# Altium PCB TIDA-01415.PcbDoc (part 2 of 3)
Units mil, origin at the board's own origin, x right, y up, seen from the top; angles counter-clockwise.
Board outline 3820.95 x 4648 mil, 4 copper layers (Top Layer, GND, PWR, Bottom Layer), stack 5.6 mil thick; 255 components, 113 nets, 599 pads, 415 vias.
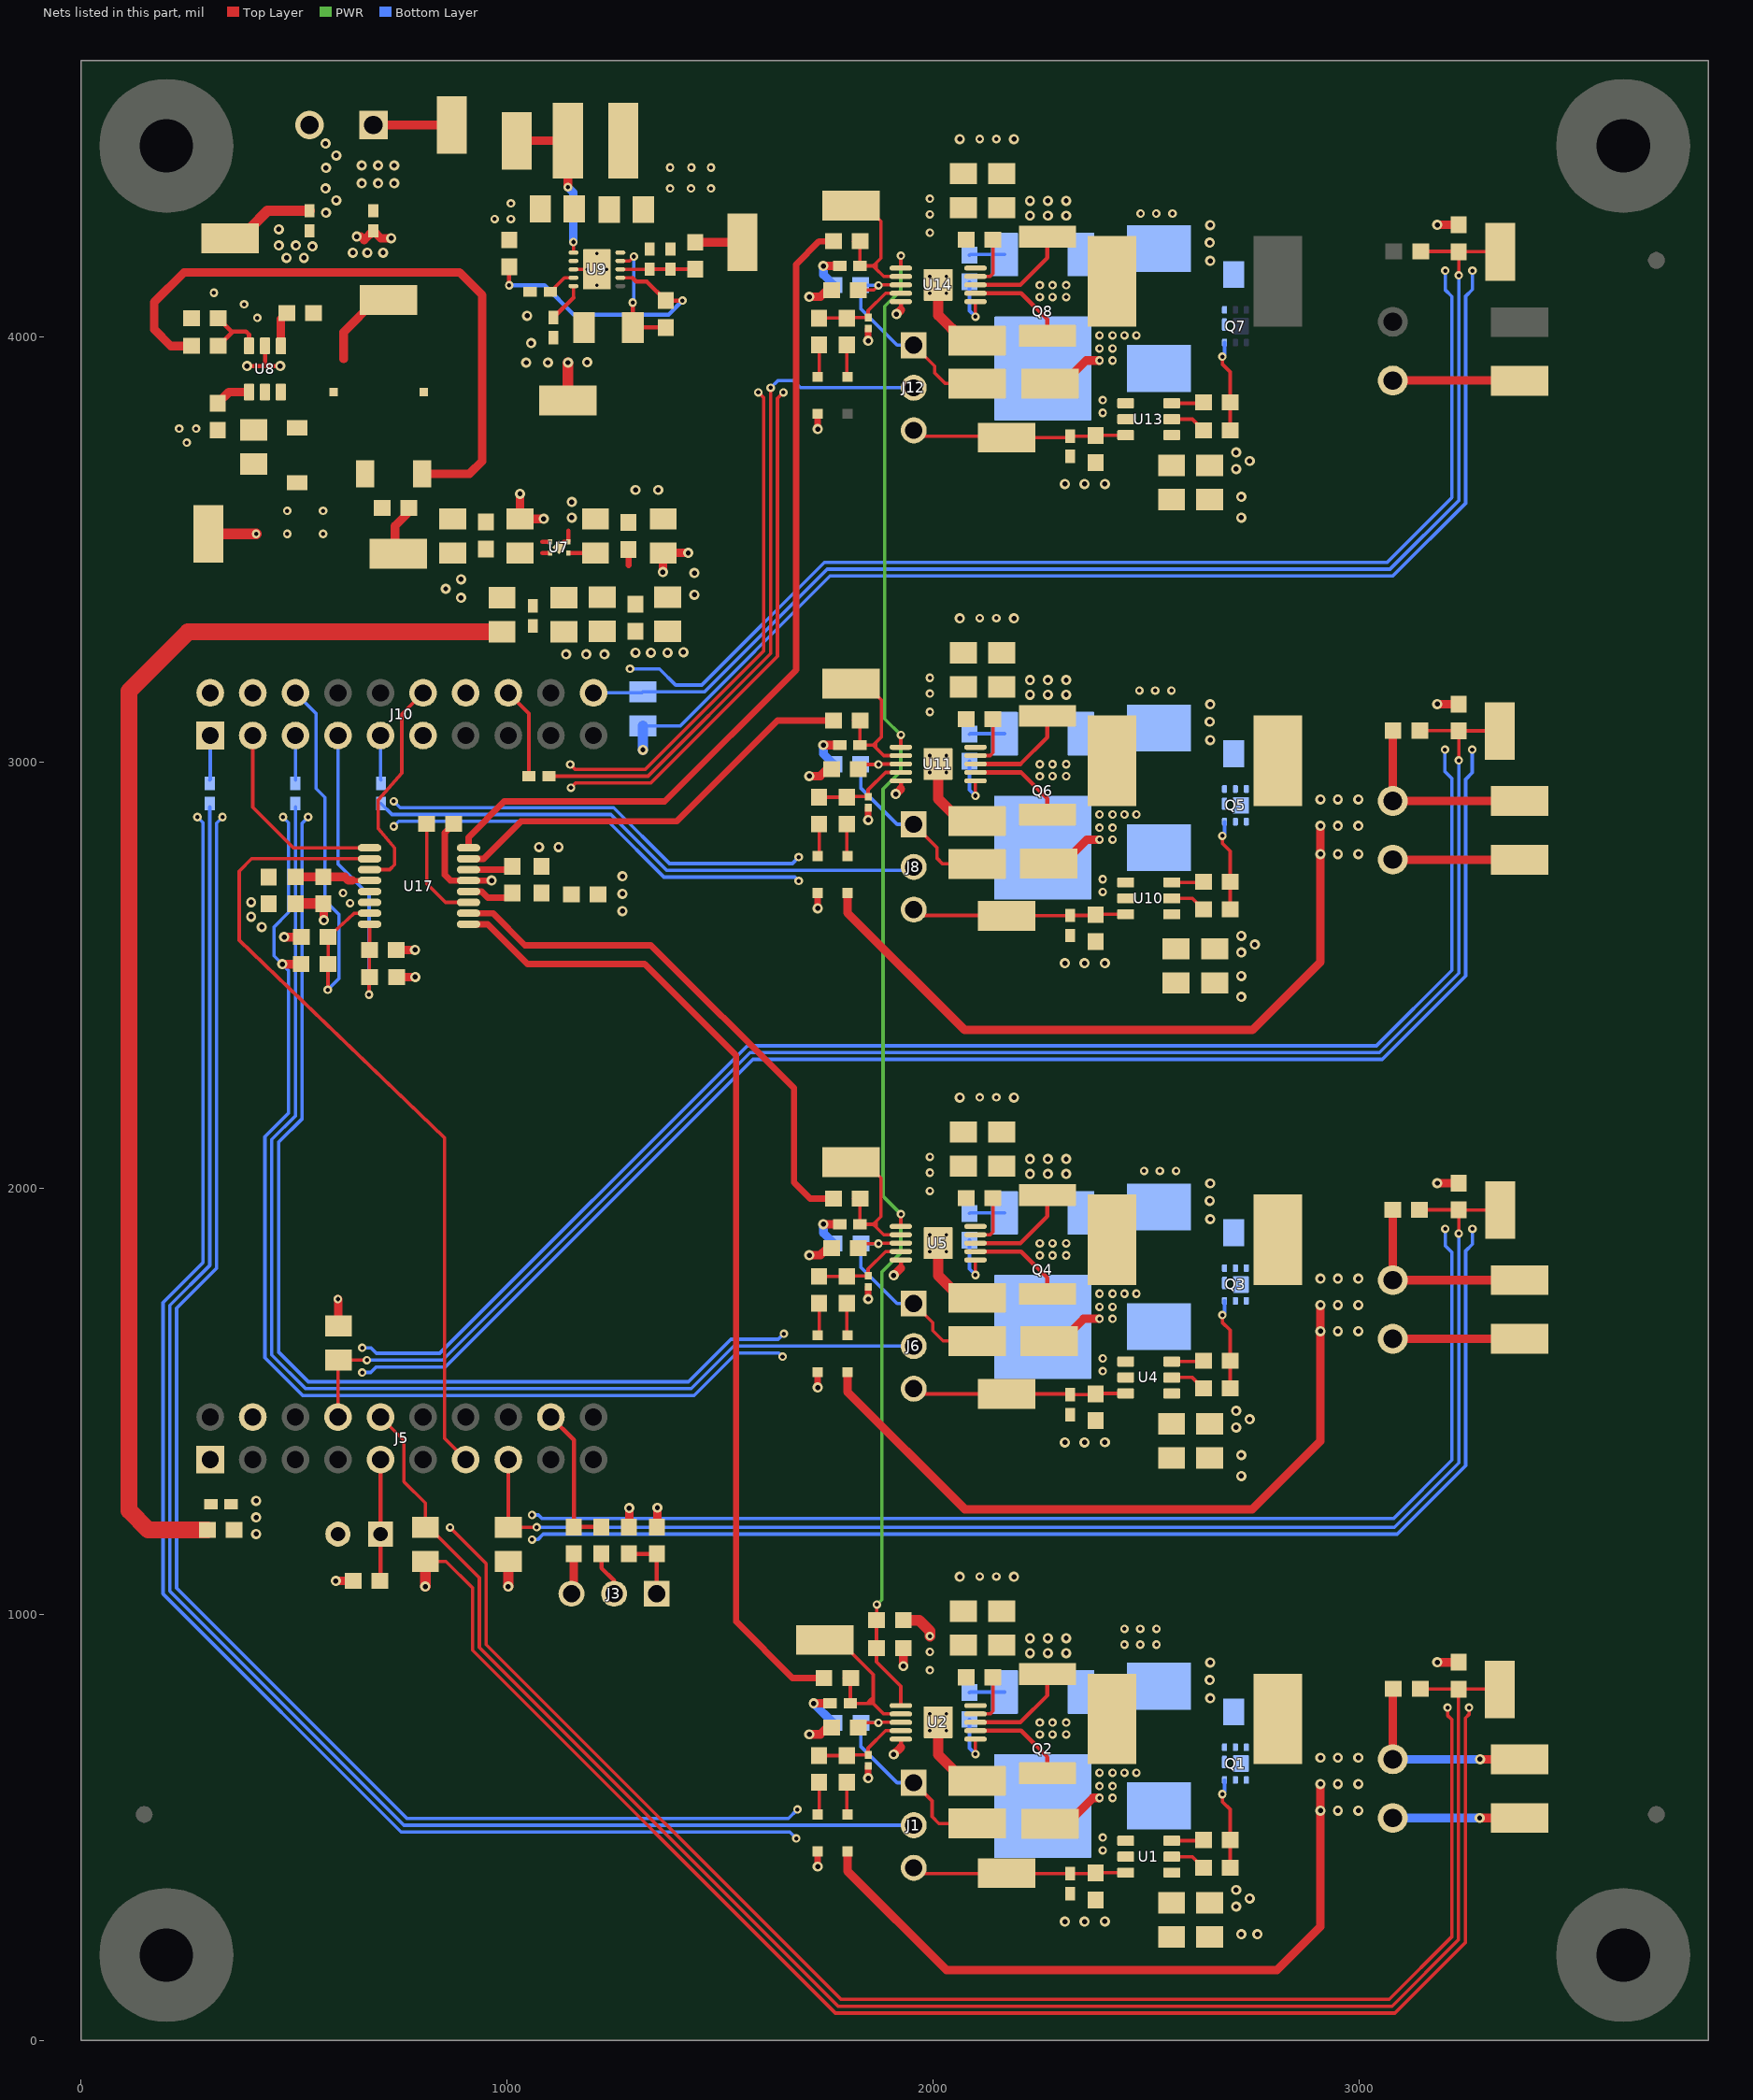
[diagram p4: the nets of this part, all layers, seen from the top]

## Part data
BLED+ BLED- GLED+ GLED- GND GND GND1 GND1 GND1 GND1 IADJ1 IADJ2 IADJ3 IADJ4 PWM1 PWM2 PWM3 PWM4 RLED+ RLED- SH1 SH2 SH3 SH4 SW1 SW2 SW3 SW4 SW5 SW6 TP1 TP3 VFB1 VFB2 VFB3 VFB4 VIN+ VIN- WLED+ WLED-: "Test Point, Miniature, SMT"
C1 C15 C46 C59 C85 C86 C87 C88: "CAP, CERM, 0.1 µF, 50 V, +/- 10%, X7R, 0805"
C2 C16 C47 C60: "CAP, CERM, 1 µF, 50 V, +/- 10%, X7R, 0805"
C3 C14 C45 C58 C74: "CAP, CERM, 1 µF, 16 V, +/- 10%, X7R, 0603"
C4 C5 C17 C18 C34 C41 C48 C49 C61 C62: "CAP, CERM, 2.2 µF, 50 V, +/- 10%, X7R, 0805"
C6 C19 C50 C63: "CAP, CERM, 0.01 µF, 50 V, +/- 10%, X7R, 0805"
C7 C20 C51 C64: "CAP, CERM, 470 pF, 50 V, +/- 10%, X7R, AEC-Q200 Grade 1, 0201"
C27: "CAP, CERM, 0.33 µF, 16 V, +/- 10%, X7R, 0603"
C28 C29 C30 C31 C35 C36 C101 C102: "CAP, CERM, 2.2 µF, 16 V, +/- 10%, X7R, 0805"
C32: "CAP, CERM, 22 µF, 16 V, +/- 10%, X5R, 1206"
C33 C38 C43 C78: "CAP, CERM, 10 µF, 10 V, +/- 20%, X6S, AEC-Q200 Grade 2, 0603"
C37: "CAP, CERM, 0.047 µF, 25 V, +/- 10%, X7R, AEC-Q200 Grade 1, 0603"
C39: "CAP, CERM, 0.1 µF, 25 V, +/- 10%, X7R, 0603"
C40: "CAP, CERM, 10 µF, 16 V, +/- 10%, X7S, AEC-Q200 Grade 1, 0805"
C42: "CAP, CERM, 0.056 µF, 16 V, +/- 10%, X7R, 0402"
C44: "CAP, CERM, 0.1 µF, 10 V, +/- 10%, X5R, 0402"
C77 C79: "CAP, CERM, 0.1 µF, 50 V, +/- 10%, X7R, 0603"
C80: "CAP, CERM, 0.15 µF, 25 V, +/- 10%, X7R, 0603"
C89 C90 C91 C92: "CAP, CERM, 0.1 µF, 25 V, +/- 20%, X7R, 0402"
C97 C98 C99 C100: "CAP, CERM, 15 pF, 50 V, +/- 5%, C0G/NP0, 0402"
D1 D3 D4 D6 D8 D10 D11 D13: "Diode, Schottky, 10 V, 0.75 A, SOD-323"
D2 D5 D9 D12: "Diode, Schottky, 60 V, 5 A, SMC"
D7: "Diode, Schottky, 100 V, 1 A, SOD-123FL"
FID1 FID2 FID3 FID4 FID5 FID6: "Fiducial mark.  There is nothing to buy or mount."
H1 H2 H3 H4: "Machine Screw, Round, #4-40 x 1/4, Nylon, Philips panhead"
H5 H6 H7 H8: "Standoff, Hex, 0.5\"L #4-40 Nylon"
J1 J3 J6 J8 J12: "Header, 2.54mm, 3x1, Tin, TH"
J2 J7 J9 J13: "Conn Term Block, 2POS, 3.5mm, TH"
J4: "Header, 100mil, 2x1, TH"
J5 J10: "Header, 100mil, 10x2, TH"
J14: "Conn Term Block, 2POS, 3.81mm, TH"
L1 L2 L8 L9: "Inductor, Shielded Drum Core, Ferrite, 47 µH, 2.7 A, 0.076 ohm, SMD"
L3: "Inductor, Shielded Drum Core, Ferrite, 15 µH, 1.15 A, 0.07 ohm, SMD"
L4 L5 L10: "Ferrite Bead, 1000 ohm @ 100 MHz, 0.6 A, 0603"
L6: "Ferrite Bead, 220 ohm @ 100 MHz, 0.45 A, 0402"
L7: "Inductor, Drum Core, Ferrite, 330 µH, 0.17 A, 6 ohm, SMD"
LBL1: library part THT-14-423-10, "Thermal Transfer Printable Labels, 0.650\" W x 0.200\" H - 10,000 per roll"
Logo2: library part Pb-Free
Q1 Q3 Q5 Q7: "MOSFET, N-CH, 100 V, 4.5 A, DQK0006C (WSON-6)"
Q2 Q4 Q6 Q8: "MOSFET, P-CH, -100 V, -4.6 A, DPAK"
R1: "RES, 5.62 k, 1%, 0.1 W, 0603"
R2: "RES, 49.9 k, 1%, 0.1 W, 0603"
R3 R4 R17 R18 R41 R42 R53 R54: "RES, 1.0, 5%, 0.1 W, 0603"
R5 R19 R43 R55: "RES, 0.3, 1%, 2 W, 2512"
R6 R7 R20 R21 R44 R45 R56 R57: "RES, 10.0 k, 1%, 0.1 W, 0603"
R8 R22 R46 R58: "RES, 470, 5%, 0.063 W, 0402"
R9 R23 R47 R59: "RES, 3.16 M, 1%, 0.1 W, 0603"
R10 R24 R48 R60: "RES, 4.53 k, 1%, 0.1 W, 0603"
R12 R25 R30 R33 R49 R61: "RES, 110 k, 1%, 0.1 W, 0603"
R14 R28 R52 R64: "RES, 14.0 k, 1%, 0.1 W, 0603"
R15 R16: "RES, 0, 5%, 0.063 W, 0402"
R29 R39 R65 R71 R86 R87 R88 R89: "RES, 100 k, 1%, 0.1 W, 0603"
R31: "RES, 30.0 k, 1%, 0.1 W, 0603"
R32 R94 R95 R96 R97: "RES, 100, 1%, 0.1 W, 0603"
R34: "RES, 887 k, 1%, 0.063 W, 0402"
R35: "RES, 1.50 k, 1%, 0.1 W, 0603"
R36: "RES, 12.4 k, 1%, 0.1 W, 0603"
R37: "RES, 124 k, 1%, 0.063 W, 0402"
R38: "RES, 182 k, 1%, 0.063 W, 0402"
R75 R76 R77 R78 R79 R80: "RES, 0, 5%, 0.1 W, 0603"
R81: "RES, 412, 1%, 0.25 W, 1206"
R99 R100: "RES, 10.0, 1%, 0.1 W, 0603"
U1 U4 U10 U13: "Single-Channel High-Speed Low-Side Gate Driver (with 4-A Peak Source and 8-A Peak Sink), DBV0006A (SOT-6)"
U2 U5 U11 U14: "PFET Buck Controller for High Power LED Drives, 10-pin eMSOP, Pb-Free"
U7: "250-mA Ultra-Low-Noise, Low-IQ LDO, DQN0004A (X2SON-4)"
U8: "Wide Input Voltage Range Buck Regulator with High Efficiency Sleep Mode, DDC0006A (SOT-6)"
U9: "3V-65V, 150mA Synchronous Buck Converter With Ultra-Low IQ, DRC0010J (VSON-10)"
U17: "12-Bit, Quad Channel, Ultra-Low Glitch, Voltage Output DAC with 2.5V, 2ppm/degC Internal Reference, PW0016A (TSSOP-16)"
ZZ1: library part AssemblyNoteLabel
ZZ2 ZZ3 ZZ4: library part AssemblyNote

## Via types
v1: diameter 24, hole 12, Top Layer to Bottom Layer, tented both sides, 213 vias
v2: diameter 20, hole 10, Top Layer to Bottom Layer, tented both sides, 182 vias
v3: diameter 19.68, hole 7.87, Top Layer to Bottom Layer, 20 vias

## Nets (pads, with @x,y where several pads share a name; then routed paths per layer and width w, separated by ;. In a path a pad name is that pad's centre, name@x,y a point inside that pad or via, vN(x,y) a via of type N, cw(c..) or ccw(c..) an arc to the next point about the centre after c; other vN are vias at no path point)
+3.3V_A: C31.1 L5.2 R32.2 R39.2 R65.2 R71.2 R99.1 | length 170.6
  Top Layer w20: v1(476.65,2590.15) R65.2@516.82,2590.15 R65.2@520.82,2590.15 ; v1(598,1078.5) R39.2@638.5,1078.5 ; R71.2@739.81,2560.15 v1(783.98,2560.15) ; R32.2@1286.46,1207.93 1287,1208.47 v1(1287,1249.5)
  other v1: 1271,2651 1271,2692 1271,2733 1301.61,3640 1355,3640
+3.3V_D: C102.1 L10.2 R100.1
  other v1: 424,2614 399,2638 399,2672 1301.77,3258 1338,3258 1377,3258 1414,3259
+3.3V_LP: C36.1 C43.1 C44.2 J5.1 L6.2 | length 3061.1
  Top Layer w40: C43.1@296.5,1198.49 157.51,1198.49 112,1244 112,3168 251,3307 C36.1@988.13,3307
+3.6V: C28.1 C32.1 C33.1 L3.2 L4.1 R30.2 TP1.1 | length 1657
  Top Layer w20: R30.2@259.11,3978.02 210.48,3978.02 171.5,4017 171.5,4080.77 241.73,4151 888,4151 941.78,4097.22 941.78,3707.78 912,3678 C32.1@800.43,3678 ; TP1.1@745,3490.07 737,3498.07 737,3555.55 769.49,3588.04 C33.1@769.49,3598
+10V: C1.1 C2.1 C15.1 C16.1 C37.1 C40.1 C46.1 C47.1 C59.1 C60.1 L7.2 R34.2 TP3.1 U1.1 U4.1 U10.1 U13.1 | length 111.2
  Top Layer w20: C37.1@1442,4221.5 TP3.1@1552.5,4221.5
  Top Layer w40: TP3.1@1552.5,4221.5 TP3.1@1553,4221
  other v1: 2712,314 2743.77,333 2712,353 2712,1439 2743.77,1458 2712,1478 2724.25,2553.98 2756.01,2572.98 2724.25,2592.98 2712,3689 2743.77,3708 2712,3728
  other v2: 1383,4348 1432,4348 1479,4348 1383,4397 1433,4397 1479,4397
BLED+: BLED+.1 C50.1 D10.2 J9.1 L8.2 Q5.1 Q5.2 Q5.5 Q5.6 Q5.8 R49.2 | length 2119.3
  Top Layer w20: D10.2@1799.43,2693.69 1799.43,2647.47 2075,2371.9 2750,2371.9 2910,2531.9 v1(2910,2785) v1(2910,2851.53) ; R49.2@3080,3074.5 J9.1@3080,2909.79 BLED+.1@3377.79,2909.79
  other v1: 2951,2785 2999,2785 2951,2851.53 2999,2851.53 2910,2913.53 2951,2913.53 2999,2913.53
CS_ADC: J10.4
CS_DAC: J10.6 R65.1 R79.2 U17.15 | length 993
  Top Layer w8: v2(579,2466.5) 579.5,2466.99 R79.2@579.5,2526.5 579.81,2526.81 R65.1@579.81,2590.15 641,2646 U17.15@677.17,2646.18
  Bottom Layer w8: J10.6@502.99,3163.49 551.57,3114.92 551.57,2939 572.3,2918.27 572.3,2676.72 605,2644.02 605,2492.5 v2(579,2466.5)
DIN: J10.12 U17.11 | length 522.9
  Top Layer w8: U17.11@677.17,2748.54 724.5,2748.54 736,2760.04 736,2799.91 697.71,2844.75 697.71,2913 753,2975.25 753,3113.5 J10.12@802.99,3163.49
DOUT_ADC: J10.14
DRDY: J10.11
GLED+: C19.1 D6.2 GLED+.1 J7.1 L2.2 Q3.1 Q3.2 Q3.5 Q3.6 Q3.8 R25.2 | length 2105.6
  Top Layer w20: D6.2@1799.43,1568.69 1799.43,1522.47 2075,1246.9 2750,1246.9 2910,1406.9 v1(2910,1665) v1(2910,1726.53) ; R25.2@3080,1949.5 J7.1@3080,1784.79 GLED+.1@3364,1784.79
  other v1: 2951,1665 2999,1665 2951,1726.53 2999,1726.53 2910,1788.53 2951,1788.53 2999,1788.53
GND: C28.2 C29.2 C30.2 C31.2 C32.2 C33.2 C34.2 C35.2 C36.2 C38.2 C39.2 C40.2 C41.2 C42.2 C43.2 C44.1 C74.2 C77.1 C78.2 C79.1 C80.1 C85.1 C86.1 C87.1 C88.1 C101.2 C102.2 D7.2 GND.1 J3.3 J4.2 J5.4 J10.2 R14.1 R16.2 R28.1 R31.1 R37.1 R38.1 R52.1 R64.1 R79.1 R80.1 R81.1 U7.2 U7.5 U8.2 U9.3 U9.10 U9.11 U17.5 U17.6 U17.13 U17.14 | length 43613.1
  Top Layer w8: C85.1@808,1124.5 856.76,1124.5 919,1062.26 919,916 1771,64 3085,64 3250.36,229.36 3250.36,756.47 3259,765.11 v2(3259,781) ; v2(866.15,1204) 951,1119.15 951,929.25 1784.25,96 3071.75,96 3218.36,242.61 3218.36,753.18 3208.54,763 v2(3208.54,781) ; v2(1148.48,2995.45) 1159.93,2984 1324.37,2984 1603,3262.63 1603,3856 v2(1590,3869) ; v2(1150.02,2941) 1161,2952 1337.63,2952 1635,3249.37 1635,3855 v2(1649,3869) v2@1650,3868 ; U9.3@1155.88,4158 v3(1188.36,4158) U9.11@1211,4158
  Top Layer w10: v1(389.5,3931) 433.5,3931 ; U8.2@431.5,3978.13 431.5,3933 433.5,3931 ; v1(467.5,3931) 433.5,3931 ; U7.5@1122.5,3505 1126.92,3505 1126.92,3511.31 1133.41,3517.8 U7.2@1143.56,3517.8 1143.56,3544.99
  Top Layer w15: C80.1@874.5,2856 854,2835.5 854,2736 867.05,2722.95 U17.5@909.46,2722.95 v1(963.95,2722.95) ; U17.6@909.46,2748.54 1004.2,2748.54 C77.1@1012.31,2756.65
  Top Layer w20: v1(472.34,2526.5) R79.1@516.5,2526.5 ; C79.1@569.97,2668 v1(570,2630) ; C79.1@570.47,2666.5 C79.1@570.97,2667 ; v2(602.99,1740.31) 604,1739.3 C87.1@604,1677 ; R80.1@740.5,2496.5 v1(784.66,2496.5) ; v1(1030.48,3631) C29.2@1030.48,3572.09 v1(1086.27,3572.09) ; J3.3@1151.46,1048.5 1156.46,1053.5 C39.2@1156.46,1142 ; C38.2@1351.46,1204.99 1353,1206.54 v1(1353,1250.5) ; v1(1366,3447) 1366,3491.59 C31.2@1366.5,3492.09 v1(1425.41,3492.09) ; v1(3184.5,887.39) R14.1@3235,887.39 ; v1(3184.5,2012.39) R28.1@3235,2012.39 ; v1(3184.5,3137.39) R52.1@3235,3137.39 ; v1(3184.5,4262.39) R64.1@3235,4262.39
  Top Layer w25: GND.1@299,3536.71 410.71,3536.71 v2(411,3537) ; C78.2@497.31,2668.66 C79.1@568.31,2668.66 ; v1(808,1065.5) C85.1@808,1124.5 ; v1(1003,1065.5) C86.1@1003,1124.5 ; GND.1@1142.53,3850 1143,3850.47 v1(1143,3939)
  Bottom Layer w8: v2(273,2872) 286,2859 286,1826.13 192.16,1732.29 192.16,1048.21 751.48,488.9 1664.1,488.9 v2(1679,474) ; v2(332,2872) 318,2858 318,1812.87 224.16,1719.03 224.16,1061.47 764.73,520.9 1660.9,520.9 v2(1682,542) ; v2(474,2872) 487,2859 487,2648 452.65,2613.65 452.65,2546.18 v1(472.34,2526.5) 487,2511.84 487,2177.13 431.47,2121.6 431.47,1602.85 520.32,1514 1439.25,1514 1539.15,1613.9 1638.1,1613.9 v2(1647,1605) ; v2(533,2872) 519,2858 519,2163.87 463.47,2108.35 463.47,1616.1 533.58,1546 1426,1546 1525.9,1645.9 1636.9,1645.9 v2(1650,1659) ; v2(659.88,1567.99) 680,1567.99 693,1580.99 855.25,1580.99 1577.25,2303 3055,2303 3251,2499 3251,2960.5 3266.5,2976 v2(3266.5,3030.5) ; v2(659.88,1625.99) 680,1625.99 693,1612.99 841.99,1612.99 1564,2335 3041.75,2335 3219,2512.25 3219,2962.5 3202.5,2979 v2(3202.5,3030.5) ; v2(734,2850) 746,2862 1237.37,2862 1368.37,2731 1676,2731 v2(1685,2722) ; v2(734,2909) 749,2894 1250.63,2894 1381.63,2763 1670,2763 v2(1685,2778) ; v2(1058.88,1175.5) 1071.99,1175.5 1084.99,1188.5 3090.5,1188.5 3251,1349 3251,1853.45 3267,1869.45 v2(3267,1905) ; v2(1058.88,1233.5) 1074,1233.5 1082,1225.5 3082.24,1225.5 3219,1362.25 3219,1850 3203,1866 v2(3203,1905) ; v2(1288.92,3220) 1358,3220 1396,3182 1457.37,3182 1745.37,3470 3066.91,3470 3219,3622.09 3219,4094 3203,4110 v2(3203,4155) ; C88.1@1319,3086 1406.63,3086 1758.63,3438 3080.16,3438 3251,3608.84 3251,4095 3267,4111 v2(3267,4155)
  Bottom Layer w25: v1(1319,3029.88) C88.1@1319,3086
  other v1: 411,1188.5 411,1227.5 411,1266.5 1075,2801.5 1121,2801.5 1139,3254 1186,3254 1229,3254 892,3387 1440,3394 856,3408 892,3430 1440,3445 1152,3575 1152,3612 1045,3939 1096,3939 1188.36,3940 1056.74,3985 1047,4049 482,4185 523,4185 543,4212 464,4214 504,4214 464,4252
  other v2: 631.31,2670 615,2693.69 484,3537 568,3537 484,3591 568,3591 413.5,4044 382.5,4076 311.5,4103
  other v3: 1211,4120.6 1233.64,4158 1211,4195.4
GND1: BLED-.1 C1.2 C2.2 C4.2 C5.2 C6.2 C7.2 C15.2 C16.2 C17.2 C18.2 C19.2 C20.2 C46.2 C47.2 C48.2 C49.2 C50.2 C51.2 C59.2 C60.2 C61.2 C62.2 C63.2 C64.2 C89.1 C90.1 C91.1 C92.1 C97.2 C98.2 C99.2 C100.2 D2.2 D5.2 D9.2 D12.2 GLED-.1 GND1.1 J2.2 J7.2 J9.2 J13.2 J14.2 Q1.4 Q1.7 Q3.4 Q3.7 Q5.4 Q5.7 Q7.4 Q7.7 R1.1 R6.1 R7.1 R16.1 R20.1 R21.1 R44.1 R45.1 R56.1 R57.1 RLED-.1 U1.4 U1.5 U2.5 U2.11 U4.4 U4.5 U5.5 U5.11 U10.4 U10.5 U11.5 U11.11 U13.4 U13.5 U14.5 U14.11 VIN-.1 WLED-.1 | length 2835.1
  Top Layer w10: 1924.75,687.89 U2.5@1924.75,707.17 ; 1924.75,1812.89 U5.5@1924.75,1832.17 ; 1924.75,2937.89 U11.5@1924.75,2957.17 ; 1924.75,4062.9 U14.5@1924.75,4082.17
  Top Layer w15: v1(1847.95,615.31) C7.2@1847.95,644.01 ; v1(1847.95,1740.31) C20.2@1847.95,1769.01 ; v1(1847.95,2865.31) C51.2@1847.95,2894.01 ; v1(1847.95,3990.31) C64.2@1847.95,4019.01
  Top Layer w20: v1(1719.98,791) C89.1@1758.76,791 ; v1(1742.98,1916) C90.1@1781.76,1916 ; v1(1742.98,3041) C91.1@1781.76,3041 ; v1(1742.98,4166) C92.1@1781.76,4166 ; v1(1908,671.14) 1924.75,687.89 ; v1(1908,1796.14) 1924.75,1812.89 ; v1(1913,2926.14) 1924.75,2937.89 ; v1(1914.62,4052.76) 1924.75,4062.9 ; J7.2@3080,1647 GLED-.1@3360,1647 ; J9.2@3080,2772 BLED-.1@3378,2772 ; J13.2@3080,3897 WLED-.1@3377,3897 ; v1(3284,522) RLED-.1@3378,522
  Top Layer w25: VIN-.1@396,4254 437.62,4295.62 R16.1@536,4295.62 ; R1.1@1930.65,986.12 1967.88,986.12 1993,961 v2(1993,949) ; U2.11@2012.35,746.54 2012.35,670.65 2074,609 GND1.1@2104,609 ; U5.11@2012.35,1871.54 2012.35,1795.65 2065,1743 GND1.1@2104,1743 ; U11.11@2012.35,2996.54 2012.35,2914.65 2064,2863 GND1.1@2101,2863 ; U14.11@2012.35,4121.54 2012.35,4050.65 2072,3991 GND1.1@2104,3991
  Bottom Layer w20: v1(1719.98,791) 1765.53,745.45 R7.1@1768.06,745.45 ; v1(1742.98,1916) 1742.98,1895.52 R20.1@1768.06,1870.45 ; v1(1742.98,3041) 1742.98,3020.52 R44.1@1767.5,2996 ; v1(1742.98,4166) 1742.98,4145.52 R56.1@1767.5,4121 ; J2.2@3080,522 v1(3284,522)
  other v1: 2724,248.9 2762,249 2310,278.82 2356,278.82 2404,279 2651,802.9 2650,845.9 2651,886.9 2063,1088.53 2190.55,1088.53 2724,1324.9 2724,1373.9 2310,1403.82 2356,1403.82 2404,1404 2651,1927.9 2650,1970.9 2651,2011.9 2063,2213.53 2190.55,2213.53 2724,2449.9 2724,2498.9 2310,2528.82 2356,2528.82 2404,2529 2651,3052.9 2650,3095.9 2651,3136.9 2063,3338.53 2190.55,3338.53 2724,3574.9 2724,3623.9 2310,3653.82 2356,3653.82 2404,3654 2651,4177.9 2650,4220.9 2651,4261.9 575,4291 599,4320 574,4348 575,4396.42 599,4425.42 574,4453.42 2063,4463.53 2190.55,4463.53
  other v2: 2399,446 2399,476 1993,869 1993,912 2450,929 2487,929 2525,929 2450,966 2487,966 2525,966 2110,1089 2149,1089 2399,1571 2399,1601 1993,1994 1993,2037 2496,2041 2533,2041 2571,2041 1993,2074 2110,2214 2149,2214 2399,2696 2399,2726 1993,3119 1993,3162 2485,3169 2522,3169 2560,3169 1993,3199 2110,3339 2149,3339 2399,3821 2399,3851 1993,4244 1993,4287 2487.65,4289 2524.65,4289 2562.65,4289 1993,4324 2110,4464 2149,4464
  other v3: 1992.67,726.85 2032.04,726.85 1992.67,766.22 2032.04,766.22 1992.67,1851.85 2032.04,1851.85 1992.67,1891.22 2032.04,1891.22 1992.67,2976.85 2032.04,2976.85 1992.67,3016.22 2032.04,3016.22 1992.67,4101.85 2032.04,4101.85 1992.67,4141.22 2032.04,4141.22
IADJ1: R94.2 U17.1 | length 2346.3
  Top Layer w15: U17.1@909.46,2620.59 954.41,2620.59 1048,2527 1323,2527 1538,2312 1538,983 1670.17,850.83 R94.2@1744.18,850.83
IADJ2: R95.2 U17.2 | length 1263.6
  Top Layer w15: U17.2@909.46,2646.18 966.82,2646.18 1042,2571 1338,2571 1674,2235 1674,2014 1711.67,1976.33 R95.2@1766.18,1976.33
IADJ3: R96.2 U17.7 | length 991.2
  Top Layer w15: U17.7@909.46,2774.13 945.13,2774.13 1033,2862 1398,2862 1634.83,3098.83 R96.2@1766.18,3098.83
IADJ4: R97.2 U17.8 | length 2018.9
  Top Layer w15: U17.8@909.46,2799.72 909.46,2824.46 993.5,2908.5 1370.02,2908.5 1679,3217.48 1679,4169.75 1733.09,4223.83 R97.2@1766.18,4223.83
LDAC: J10.7 R71.1 R80.2 U17.16 | length 805.8
  Top Layer w8: v2(676,2455) 676,2494 678,2496 R80.2@677.5,2496.5 676.82,2497.18 R71.1@676.82,2560.15 677.17,2560.51 U17.16@677.17,2620.59
  Bottom Layer w8: J10.7@602.99,3063.49 602.99,2761.57 676,2688.56 v2(676,2455)
NetC3_2: C3.2 U2.9 | length 123
  Top Layer w8: U2.9@2099.95,766.22 2134.08,766.22 2141.25,773.39 C3.2@2141.25,852.17
NetC7_1: C7.1 R9.2 R10.1 U2.4 | length 225.4
  Top Layer w8: R9.2@1732.95,668.5 R10.1@1797.95,668.5 1799.45,669.99 C7.1@1847.95,669.99 1847.95,686.09 1888.71,726.85 U2.4@1924.75,726.85
NetC14_2: C14.2 U5.9 | length 123
  Top Layer w8: U5.9@2099.95,1891.22 2134.08,1891.22 2141.25,1898.39 C14.2@2141.25,1977.17
NetC20_1: C20.1 R23.2 R24.1 U5.4 | length 225.4
  Top Layer w8: R23.2@1732.95,1793.5 R24.1@1797.95,1793.5 1799.45,1794.99 C20.1@1847.95,1794.99 1847.95,1811.09 1888.71,1851.85 U5.4@1924.75,1851.85
NetC27_1: C27.1 D7.1 L3.1 SW5.1 U8.6 | length 198.7
  Top Layer w20: 616.26,3948 616.26,4010.26 692.42,4086.42 SW5.1@721.11,4086.42
NetC27_2: C27.2 U8.1 | length 82.7
  Top Layer w20: U8.1@468.9,3978.13 468.9,4040.9 C27.2@483,4055
NetC29_1: C29.1 L4.2 U7.3 U7.4 | length 37.7
  Top Layer w10: 1082.5,3492.2 U7.4@1101.44,3492.2 ; 1082.64,3517.8 U7.3@1101.44,3517.8
NetC30_1: C30.1 C35.1 C101.1 L5.1 L6.1 L10.1 U7.1 | length 100.5
  Top Layer w10: U7.1@1143.56,3492.2 1143.67,3492.09 C30.1@1207.5,3492.09
  Top Layer w15: 1285.5,3464 L5.1@1285.5,3500.5
NetC37_2: C37.2 R34.1 R37.2 U9.8 | length 176.1
  Top Layer w8: U9.8@1266.12,4158 1334.62,4158 R37.2@1335,4158.38 R34.1@1384,4158.38 1441.87,4158.38 C37.2@1442,4158.5
NetC38_1: C38.1 J3.1 R32.1 | length 158.5
  Top Layer w10: R32.1@1286.46,1142 C38.1@1351.46,1142 J3.1@1351.46,1048.5
NetC42_1: C42.1 U9.4 | length 68.1
  Top Layer w8: C42.1@1101.62,4105 1134.94,4138.32 U9.4@1155.88,4138.32
NetC45_2: C45.2 U11.9 | length 123
  Top Layer w8: U11.9@2099.95,3016.22 2134.08,3016.22 2141.25,3023.39 C45.2@2141.25,3102.17
NetC51_1: C51.1 R47.2 R48.1 U11.4 | length 225.4
  Top Layer w8: R47.2@1732.95,2918.5 R48.1@1797.95,2918.5 1799.45,2919.99 C51.1@1847.95,2919.99 1847.95,2936.09 1888.71,2976.85 U11.4@1924.75,2976.85
NetC58_2: C58.2 U14.9 | length 123
  Top Layer w8: U14.9@2099.95,4141.22 2134.08,4141.22 2141.25,4148.39 C58.2@2141.25,4227.17
NetC64_1: C64.1 R59.2 R60.1 U14.4 | length 225.4
  Top Layer w8: R59.2@1732.95,4043.5 R60.1@1797.95,4043.5 1799.45,4044.99 C64.1@1847.95,4044.99 1847.95,4061.09 1888.71,4101.85 U14.4@1924.75,4101.85
NetC74_1: C74.1 C77.2 R99.2 U17.4 | length 113.2
  Top Layer w15: U17.4@909.46,2697.36 940.17,2697.36 954.53,2683 1001.66,2683 C77.2@1012.31,2693.66
NetC78_1: C78.1 C79.2 R100.2 U17.12 | length 177.5
  Top Layer w12: 636.45,2722.95 U17.12@677.17,2722.95
  Top Layer w20: C78.1@503.31,2731.65 C79.2@568.31,2731.65 618.85,2731.65 627.55,2722.95 636.45,2722.95
NetC80_2: C80.2 U17.3 | length 256.6
  Top Layer w8: C80.2@811.5,2856 811.5,2715.5 855.23,2671.77 U17.3@909.46,2671.77
NetC89_2: C89.2 IADJ1.1 R94.1 U2.2 | length 438.7
  Top Layer w8: IADJ1.1@1746.31,940 1778.64,940 1859.75,858.88 1859.75,805.1 ; R94.1@1791.42,850.83 1806,836.26 C89.2@1806,791 1845.65,791 ; U2.2@1924.75,766.22 1884.53,766.22 1859.75,791 ; 1845.65,791 1859.75,791 ; 1845.65,791 1853.42,798.77 ; 1853.42,798.77 1859.75,792.44 ; 1853.42,798.77 1859.75,805.1 ; 1859.75,791 1859.75,792.44 ; 1859.75,792.44 1859.75,805.1
NetC90_2: C90.2 IADJ2.1 R95.1 U5.2 | length 388.9
  Top Layer w8: IADJ2.1@1808,2062 1841,2062 1878,2025 1878,1934.25 1866.75,1923 ; R95.1@1813.42,1976.33 1829,1960.75 C90.2@1829,1916 1859.75,1916 ; IADJ2.1@1829,2064.37 IADJ2.1@1829.17,2064.2 ; U5.2@1924.75,1891.22 1884.53,1891.22 1866.75,1909 ; 1859.75,1916 1866.75,1909 ; 1859.75,1916 1866.75,1923 ; 1866.75,1909 1866.75,1923
NetC91_2: C91.2 IADJ3.1 R96.1 U11.2 | length 383.5
  Top Layer w8: IADJ3.1@1808,3185 1841,3185 1879,3147 1879,3060.25 1866,3047.25 ; R96.1@1813.42,3098.83 1829,3083.26 C91.2@1829,3041 1859.75,3041 ; U11.2@1924.75,3016.22 1884.53,3016.22 1866,3034.75 ; 1859.75,3041 1866,3034.75 ; 1859.75,3041 1866,3047.25 ; 1866,3034.75 1866,3047.25
NetC92_2: C92.2 IADJ4.1 R97.1 U14.2 | length 382
  Top Layer w8: IADJ4.1@1808,4307.95 1841,4307.95 1878,4270.95 1878,4184.25 1866.88,4173.12 ; R97.1@1813.42,4223.83 1829,4208.26 C92.2@1829,4166 1859.75,4166 ; U14.2@1924.75,4141.22 1884.53,4141.22 1866.2,4159.55 ; 1859.75,4166 1866.2,4159.55 ; 1859.75,4166 1866.88,4173.12 ; 1866.2,4159.55 1866.88,4160.23 1866.88,4173.12
NetD1_1: D1.1 R9.1 | length 76.7
  Top Layer w8: D1.1@1729.43,530.31 1732.95,533.83 R9.1@1732.95,605.5
NetD2_1: D2.1 L1.1 Q2.4 SW1.1 | length 141.3
  Top Layer w20: SW1.1@2275,508 2315,508 2376,569 v2(2391,569)
  other v2: 2422,569 2391,597 2422,597 2391,628 2422,628 2450,628 2478,628
NetD3_1: D3.1 R10.2 | length 75.8
  Top Layer w8: R10.2@1797.95,605.5 1797.95,531.78 D3.1@1799.43,530.31
NetD4_1: D4.1 R23.1 | length 76.7
  Top Layer w8: D4.1@1729.43,1655.31 1732.95,1658.83 R23.1@1732.95,1730.5
NetD5_1: D5.1 L2.1 Q4.4 SW2.1 | length 139.5
  Top Layer w20: SW2.1@2273,1642 2301.8,1642 2353.8,1694 v2(2391,1694)
  other v2: 2422,1694 2391,1722 2422,1722 2391,1753 2422,1753 2450,1753 2478,1753
NetD6_1: D6.1 R24.2 | length 75.8
  Top Layer w8: R24.2@1797.95,1730.5 1797.95,1656.78 D6.1@1799.43,1655.31
NetD8_1: D8.1 R47.1 | length 76.7
  Top Layer w8: D8.1@1729.43,2780.31 1732.95,2783.83 R47.1@1732.95,2855.5
NetD9_1: D9.1 L8.1 Q6.4 SW3.1 | length 142.4
  Top Layer w20: SW3.1@2272,2762.5 2305,2762.5 2361.5,2819 v2(2391,2819)
  other v2: 2422,2819 2391,2847 2422,2847 2391,2878 2422,2878 2450,2878 2478,2878
NetD10_1: D10.1 R48.2 | length 75.8
  Top Layer w8: R48.2@1797.95,2855.5 1797.95,2781.78 D10.1@1799.43,2780.31
NetD11_1: D11.1 R59.1 | length 76.7
  Top Layer w8: D11.1@1729.43,3905.31 1732.95,3908.83 R59.1@1732.95,3980.5
NetD12_1: D12.1 L9.1 Q8.4 SW4.1 | length 138.4
  Top Layer w20: SW4.1@2275,3890 2306,3890 2360,3944 v2(2391,3944)
  other v2: 2422,3944 2391,3972 2422,3972 2391,4003 2422,4003 2450,4003 2478,4003
NetD13_1: D13.1 R60.2 | length 75.8
  Top Layer w8: R60.2@1797.95,3980.5 1797.95,3906.78 D13.1@1799.43,3905.31
NetJ3_2: J3.2 R35.2 | length 105.9
  Top Layer w10: R35.2@1221.46,1142 1221.46,1109.04 1251.46,1079.04 J3.2@1251.46,1048.5
NetJ4_1: J4.1 J5.9 R39.1 | length 285.6
  Top Layer w10: R39.1@701.5,1078.5 702.99,1080 J4.1@702.99,1188.49 J5.9@702.99,1363.49
NetJ10_1: J10.1 R8.1 | length 104.9
  Bottom Layer w8: R8.1@302,2959 302.99,2959.99 J10.1@302.99,3063.49
NetJ10_5: J10.5 R22.1 | length 104.5
  Bottom Layer w8: R22.1@502.99,2959 J10.5@502.99,3063.49
NetJ10_9: J10.9 R46.1 | length 104.9
  Bottom Layer w8: J10.9@702.99,3063.49 702.99,2960 R46.1@704,2959
NetJ10_16: J10.16 R58.1 | length 215.5
  Top Layer w8: J10.16@1002.99,3163.49 1051.38,3115.11 R58.1@1051.38,2968
NetL7_1: L7.1 SW6.1 U9.1 | length 388.1
  Top Layer w8: L7.1@1143.04,4460 L7.1@1143.04,4460 ; U9.1@1155.88,4197.37 v2(1155.88,4222)
  Top Layer w20: SW6.1@1022.94,4459.96 1022.98,4460 L7.1@1143.04,4460 ; v2(1143,4351) L7.1@1143.04,4460
  Bottom Layer w20: v2(1143,4351) 1155.88,4338.12 v2(1155.88,4222)
NetQ1_3: Q1.3 R3.1 R4.1 | length 215.5
  Top Layer w8: v2(2679.71,577.9) 2679.71,560.59 2698.22,542.09 R4.1@2698.22,470.37 R3.1@2698.22,405.37
  Bottom Layer w8: v2(2679.71,577.9) 2684.82,583 Q1.3@2684.82,611.13
NetQ2_1: Q2.1 R75.2 | length 82.8
  Bottom Layer w8: R75.2@2086,816.39 2087.36,817.76 Q2.1@2168.24,817.76
NetQ2_3: Q2.3 R5.1 U2.7 | length 232.3
  Top Layer w10: U2.7@2099.95,726.85 2207.15,726.85 2269,665 R5.1@2269,627.39
  other v2: 2251,717.9 2281,718 2313,718 2251,746 2281,746 2313,746
NetQ3_3: Q3.3 R17.1 R18.1 | length 215.5
  Top Layer w8: v2(2679.71,1702.9) 2679.71,1685.59 2698.22,1667.09 R18.1@2698.22,1595.37 R17.1@2698.22,1530.37
  Bottom Layer w8: v2(2679.71,1702.9) 2684.82,1708 Q3.3@2684.82,1736.13
NetQ4_1: Q4.1 R76.2 | length 82.8
  Bottom Layer w8: R76.2@2086,1941.39 2087.36,1942.76 Q4.1@2168.24,1942.76
NetQ4_3: Q4.3 R19.1 U5.7 | length 271.1
  Top Layer w10: U5.7@2099.95,1851.85 2207.15,1851.85 2269,1790 R19.1@2269,1752.39 R19.1@2230.14,1752.39
  other v2: 2251,1842.9 2281,1843 2313,1843 2251,1871 2281,1871 2313,1871
NetQ5_3: Q5.3 R41.1 R42.1 | length 215.5
  Top Layer w8: v2(2679.71,2827.9) 2679.71,2810.59 2698.22,2792.09 R42.1@2698.22,2720.37 R41.1@2698.22,2655.37
  Bottom Layer w8: v2(2679.71,2827.9) 2684.82,2833 Q5.3@2684.82,2861.13
NetQ6_1: Q6.1 R77.2 | length 82.8
  Bottom Layer w8: R77.2@2086,3066.39 2087.36,3067.76 Q6.1@2168.24,3067.76
NetQ6_3: Q6.3 R43.1 U11.7 | length 271.1
  Top Layer w10: U11.7@2099.95,2976.85 2207.15,2976.85 2269,2915 R43.1@2269,2877.39 R43.1@2230.14,2877.39
  other v2: 2251,2967.9 2281,2968 2313,2968 2251,2996 2281,2996 2313,2996
NetQ7_3: Q7.3 R53.1 R54.1 | length 215.5
  Top Layer w8: v2(2679.71,3952.9) 2679.71,3935.59 2698.22,3917.09 R54.1@2698.22,3845.37 R53.1@2698.22,3780.37
  Bottom Layer w8: v2(2679.71,3952.9) 2684.82,3958 Q7.3@2684.82,3986.13
NetQ8_1: Q8.1 R78.2 | length 82.8
  Bottom Layer w8: R78.2@2086,4191.39 2087.36,4192.76 Q8.1@2168.24,4192.76
NetQ8_3: Q8.3 R55.1 U14.7 | length 271.1
  Top Layer w10: U14.7@2099.95,4101.85 2207.15,4101.85 2269,4040 R55.1@2269,4002.39 R55.1@2230.14,4002.39
  other v2: 2251,4092.9 2281,4093 2313,4093 2251,4121 2281,4121 2313,4121
NetR3_2: R3.2 U1.2 | length 84.9
  Top Layer w8: U1.2@2561.06,431.17 2609.43,431.17 R3.2@2635.23,405.37
NetR4_2: R4.2 U1.3 | length 74.9
  Top Layer w8: U1.3@2561.06,468.57 2633.42,468.57 R4.2@2635.23,470.37
NetR17_2: R17.2 U4.2 | length 84.9
  Top Layer w8: U4.2@2561.06,1556.17 2609.43,1556.17 R17.2@2635.23,1530.37
NetR18_2: R18.2 U4.3 | length 74.9
  Top Layer w8: U4.3@2561.06,1593.57 2633.42,1593.57 R18.2@2635.23,1595.37
NetR29_1: R29.1 U8.4 | length 84.5
  Top Layer w20: R29.1@320.5,3843.5 346.87,3869.87 U8.4@394.1,3869.87
NetR30_1: R30.1 R31.2 U8.3 | length 159.6
  Top Layer w10: R30.1@322.11,3978.02 356.09,4012 386.97,4012 394.1,4004.87 U8.3@394.1,3978.13 ; R31.2@322.11,4043.02 353.12,4012
NetR33_1: R33.1 R36.2 U9.7 | length 660.6
  Top Layer w8: U9.7@1266.12,4138.32 1294.68,4138.32
  Top Layer w10: v2(1005,4120.6) R33.1@1005,4163.96 ; 1294.68,4138.32 1303.37,4129.63 1327.87,4129.63 R36.2@1373,4084.5 v2(1412,4084.5)
  Bottom Layer w10: v2(1005,4120.6) 1087.94,4120.6 1156.74,4051.8 1379.31,4051.8 v2(1412,4084.5)
NetR36_1: R36.1 R81.2 U9.9 | length 281.8
  Top Layer w8: U9.9@1266.12,4177.69 1287.69,4177.69 v2(1298,4188)
  Top Layer w10: v2(1295.09,4080) R81.2@1295.09,4021.5 R36.1@1373,4021.5
  Bottom Layer w8: v2(1295.09,4080) 1298,4082.91 v2(1298,4188)
NetR38_2: R38.2 U9.5 | length 93.4
  Top Layer w8: 1155.88,4091.5 U9.5@1155.88,4118.63
  Top Layer w10: R38.2@1109,4044.62 1155.88,4091.5
NetR41_2: R41.2 U10.2 | length 84.9
  Top Layer w8: U10.2@2561.06,2681.17 2609.43,2681.17 R41.2@2635.23,2655.37
NetR42_2: R42.2 U10.3 | length 74.9
  Top Layer w8: U10.3@2561.06,2718.57 2633.42,2718.57 R42.2@2635.23,2720.37
NetR53_2: R53.2 U13.2 | length 84.9
  Top Layer w8: U13.2@2561.06,3806.17 2609.43,3806.17 R53.2@2635.23,3780.37
NetR54_2: R54.2 U13.3 | length 74.9
  Top Layer w8: U13.3@2561.06,3843.57 2633.42,3843.57 R54.2@2635.23,3845.37
NetR75_1: R75.1 U2.6 | length 122.6
  Top Layer w8: U2.6@2099.95,707.17 v2(2100,671.9) v2(2100,671.9)
  Bottom Layer w8: R75.1@2086,753.4 2086,685.9 v2(2100,671.9)
NetR76_1: R76.1 U5.6 | length 122.6
  Top Layer w8: U5.6@2099.95,1832.17 v2(2100,1796.9) v2(2100,1796.9)
  Bottom Layer w8: R76.1@2086,1878.4 2086,1810.9 v2(2100,1796.9)
NetR77_1: R77.1 U11.6 | length 122.6
  Top Layer w8: U11.6@2099.95,2957.17 v2(2100,2921.9) v2(2100,2921.9)
  Bottom Layer w8: R77.1@2086,3003.4 2086,2935.9 v2(2100,2921.9)
NetR78_1: R78.1 U14.6 | length 122.6
  Top Layer w8: U14.6@2099.95,4082.17 v2(2100,4046.9) v2(2100,4046.9)
  Bottom Layer w8: R78.1@2086,4128.4 2086,4060.9 v2(2100,4046.9)
PWM1: J1.1 PWM1.1 R7.2 R86.1 U2.3 | length 581.2
  Top Layer w8: R86.1@1824.92,734.48 1835.89,745.45 v2(1872.31,745.45) 1873.4,746.54 U2.3@1924.75,746.54 ; J1.1@1955,604.9 1998,561.9 1998,525 2014,509 PWM1.1@2104,509
  Bottom Layer w8: R7.2@1830.5,746 1830.5,690.5 1916.1,604.9 J1.1@1955,604.9 J1.1@1961.5,611.4 ; R7.2@1831.05,745.45 v2(1872.31,745.45) v2@1872.38,745.37
PWM2: J6.1 PWM2.1 R20.2 R87.1 U5.3 | length 567.2
  Top Layer w8: R87.1@1824.92,1859.48 1835.89,1870.45 v2(1872.31,1870.45) 1873.4,1871.54 U5.3@1924.75,1871.54 ; J6.1@1955,1729.9 2000,1684.9 2000,1666 2024,1642 PWM2.1@2104,1642
  Bottom Layer w8: R20.2@1830.5,1871 1830.5,1815.5 1916.1,1729.9 J6.1@1955,1729.9 J6.1@1961.5,1736.4 ; R20.2@1831.05,1870.45 v2(1872.31,1870.45)
PWM3: J8.1 PWM3.1 R44.2 R88.1 U11.3 | length 569.8
  Top Layer w8: R88.1@1824.92,2984.48 1835.89,2995.45 v2(1872.31,2995.45) 1873.4,2996.54 U11.3@1924.75,2996.54 ; J8.1@1955,2854.9 2010,2799.9 2010,2775 2023,2762 PWM3.1@2101,2762
  Bottom Layer w8: R44.2@1830.5,2996 1830.5,2940.5 1916.1,2854.9 J8.1@1955,2854.9 J8.1@1961.5,2861.4 ; R44.2@1831.05,2995.45 v2(1872.31,2995.45)
PWM4: J12.1 PWM4.1 R56.2 R89.1 U14.3 | length 567.1
  Top Layer w8: R89.1@1824.92,4109.48 1861.34,4109.48 v2(1872.31,4120.45) 1873.4,4121.54 U14.3@1924.75,4121.54 ; J12.1@1955,3979.9 2004,3930.9 2004,3915 2029,3890 PWM4.1@2104,3890
  Bottom Layer w8: v2(1872.31,4120.45) 1831.05,4120.45 R56.2@1830.5,4121 1830.5,4065.5 1916.1,3979.9 J12.1@1955,3979.9 J12.1@1961.5,3986.4
RLED+: C6.1 D3.2 J2.1 L1.2 Q1.1 Q1.2 Q1.5 Q1.6 Q1.8 R12.2 RLED+.1 | length 2088.4
  Top Layer w20: D3.2@1799.43,443.69 1799.43,397.47 2031.9,165 2808,165 2910,267 v1(2910,539) v1(2910,601.53) ; J2.1@3080,659.79 R12.2@3080,820.5 ; v1(3285,659.79) RLED+.1@3377.79,659.79
  Bottom Layer w20: J2.1@3080,659.79 v1(3285,659.79)
  other v1: 2951,539 2999,539 2951,601.53 2999,601.53 2910,663.53 2951,663.53 2999,663.53
SCLK: J5.13 U17.10 | length 1925.5
  Top Layer w8: U17.10@677.17,2774.13 400.13,2774.13 371,2745 371,2583 853,2119 853,1413.49 J5.13@902.99,1363.49
SHPWM1: C97.1 J1.3 R6.2 SH1.1 U1.6 | length 504.7
  Top Layer w8: J1.3@1955,404.9 1968.83,391.07 SH1.1@2171.5,391.07 ; R6.2@2380.33,391.07 C97.1@2322.48,391.07 SH1.1@2174.25,391.07 ; R6.2@2383.03,393.76 U1.6@2452.79,393.76 ; SH1.1@2171.5,391.07 SH1.1@2172.88,392.45 SH1.1@2174.25,391.07 ; SH1.1@2171.5,391.07 SH1.1@2174.25,391.07
SHPWM2: C98.1 J6.3 R21.2 SH2.1 U4.6 | length 500.8
  Top Layer w8: J6.3@1955,1529.9 1967.24,1517.66 SH2.1@2172.88,1517.66 2320.89,1517.66 C98.1@2322.48,1516.07 R21.2@2380.33,1516.07 ; R21.2@2383.03,1518.76 U4.6@2452.79,1518.76
SHPWM3: C99.1 J8.3 R45.2 SH3.1 U10.6 | length 501.6
  Top Layer w8: J8.3@1955,2654.9 1968.83,2641.07 2171.98,2641.07 SH3.1@2172.88,2640.17 2321.58,2640.17 C99.1@2322.48,2641.07 R45.2@2380.33,2641.07 ; R45.2@2383.03,2643.76 U10.6@2452.79,2643.76
SHPWM4: C100.1 J12.3 R57.2 SH4.1 U13.6 | length 503.4
  Top Layer w8: J12.3@1955,3779.9 1968.83,3766.07 2169.81,3766.07 SH4.1@2172.88,3763 2319.41,3763 C100.1@2322.48,3766.07 R57.2@2380.33,3766.07 ; R57.2@2383.03,3768.76 U13.6@2452.79,3768.76
SPWM1: J1.2 R8.2 | length 3854.7
  Bottom Layer w8: R8.2@302,2896 302,1819.5 208.16,1725.66 208.16,1054.84 758.1,504.9 J1.2@1955,504.9
SPWM2: J6.2 R22.2 | length 2891.4
  Bottom Layer w8: R22.2@503,2896 503,2170.5 447.47,2114.97 447.47,1609.48 526.95,1530 1432.63,1530 1532.52,1629.9 J6.2@1955,1629.9
SPWM3: J8.2 R46.2 | length 1319.3
  Bottom Layer w8: R46.2@704,2903.88 729.88,2878 1244,2878 1375,2747 1947.1,2747 J8.2@1955,2754.9
SPWM4: J12.2 R58.2 | length 1613.8
  Top Layer w8: R58.2@1098.62,2968 1331,2968 1619,3256 v2(1619,3880)
  Bottom Layer w8: v2(1619,3880) 1635.96,3896.96 1672.04,3896.96 1689,3880 1954.9,3880 J12.2@1955,3879.9
SYNC_DAC: J10.3 U17.9 | length 482.1
  Top Layer w8: J10.3@402.99,3063.49 402.99,2895.01 498.28,2799.72 U17.9@677.17,2799.72
TEMP: C39.1 J5.18 R35.1 | length 346.1
  Top Layer w10: J5.18@1102.99,1463.49 1157,1409.49 1157,1205.54 C39.1@1156.46,1205 R35.1@1221.46,1205
UVLO: R1.2 R2.2 U2.1 U5.1 U11.1 U14.1 | length 3604.1
  Top Layer w8: v2(1868.4,1022.95) 1868.4,986.86 R1.2@1867.66,986.12 R2.2@1867.66,921.12 1867.66,888.34 1924.75,831.25 U2.1@1924.75,785.91 ; U5.1@1924.75,1910.91 v2(1924.75,1939.9) ; U11.1@1924.75,3035.91 v2(1924.75,3064.9) ; U14.1@1924.75,4160.91 v2(1924.75,4189.9)
  PWR w8: v2(1868.4,1022.95) 1880,1034.56 1880,1804 1924.75,1848.75 v2(1924.75,1939.9) 1883,1981.65 1883,2938 1924.75,2979.75 v2(1924.75,3064.9) 1887,3102.65 1887,4071 1924.75,4108.75 v2(1924.75,4189.9)
VFB1: C85.2 J5.10 R12.1 R14.2 VFB1.1 | length 4129.6
  Top Layer w8: J5.10@702.99,1463.49 758,1408.49 758,1311.5 808,1261.5 C85.2@808,1204.5 816.5,1204.5 935,1086 935,922.63 1777.63,80 3078.37,80 3234.36,235.99 3234.36,823.76 R14.2@3235,824.4 3330.6,824.4 VFB1.1@3331,824 ; R12.1@3144.5,825 3233.5,825 R14.2@3234.1,824.4
VFB2: C86.2 J5.15 R25.1 R28.2 VFB2.1 | length 3237.3
  Top Layer w8: J5.15@1002.99,1363.49 C86.2@1003,1204.5 v2(1069.88,1204.5) ; R25.1@3142.5,1950 3234.4,1950 R28.2@3235,1949.4 ; v2(3235,1894) R28.2@3235,1949.4 ; VFB2.1@3332,1949 3331.6,1949.4 R28.2@3235,1949.4
  Bottom Layer w8: v2(1069.88,1204.5) 3083.87,1204.5 3235,1355.63 v2(3235,1894)
VFB3: C87.2 J5.8 R49.1 R52.2 VFB3.1 | length 3897.4
  Top Layer w8: J5.8@602.99,1463.49 602.99,1595.99 C87.2@604,1597 v2(670.88,1596.99) ; R49.1@3143.5,3075 3234.4,3075 R52.2@3235,3074.4 ; v2(3235,3005) R52.2@3235,3074.4 ; VFB3.1@3330.6,3074.4 R52.2@3235,3074.4
  Bottom Layer w8: v2(670.88,1596.99) 848.62,1596.99 1570.63,2319 3048.37,2319 3235,2505.63 v2(3235,3005)
VFB4: C88.2 J10.20 R61.1 R64.2 VFB4.1 | length 2989.5
  Top Layer w8: R61.1@3145.5,4200 3234.4,4200 R64.2@3235,4199.4 ; v2(3235,4144) R64.2@3235,4199.4 ; VFB4.1@3331.6,4199.4 R64.2@3235,4199.4
  Bottom Layer w8: J10.20@1202.99,3163.49 1316.49,3163.49 C88.2@1319,3166 1464,3166 1752,3454 3073.53,3454 3235,3615.47 v2(3235,4144)
VIN_LED: C3.1 C4.1 C5.1 C14.1 C17.1 C18.1 C45.1 C48.1 C49.1 C58.1 C61.1 C62.1 D1.2 D4.2 D8.2 D11.2 J14.1 R2.1 R5.2 R15.1 R19.2 R43.2 R55.2 R86.2 R87.2 R88.2 R89.2 U2.8 U2.10 U5.8 U5.10 U11.8 U11.10 U14.8 U14.10 VIN+.1 | length 1720.2
  Top Layer w10: U2.8@2099.95,746.54 2205.54,746.54 2269,810 R5.2@2269,859.67 ; U5.8@2099.95,1871.54 2205.54,1871.54 2269,1935 R19.2@2269,1984.67 R19.2@2224.22,1984.67 ; U11.8@2099.95,2996.54 2205.54,2996.54 2269,3060 R43.2@2269,3109.67 R43.2@2224.22,3109.67 ; U14.8@2099.95,4121.54 2205.54,4121.54 2269,4185 R55.2@2269,4234.67 R55.2@2224.22,4234.67
  Top Layer w15: v1(1729.43,407.83) D1.2@1729.43,443.69 ; v1(1729.43,1532.83) D4.2@1729.43,1568.69 ; v1(1729.43,2657.83) D8.2@1729.43,2693.69 ; v1(1729.43,3782.83) D11.2@1729.43,3818.69
  Top Layer w20: J14.1@686,4497 VIN+.1@870,4497 ; v1(1709.67,718.36) 1735.67,718.36 1751.79,734.48 R86.2@1761.93,734.48 ; v1(1709.67,1843.36) 1735.67,1843.36 1751.79,1859.48 R87.2@1761.93,1859.48 ; v1(1709.67,2968.36) 1735.67,2968.36 1751.79,2984.48 R88.2@1761.93,2984.48 ; v1(1709.67,4093.36) 1735.67,4093.36 1751.79,4109.48 R89.2@1761.93,4109.48 ; v1(1930.65,878.45) R2.1@1930.65,921.12
  other v1: 2228,909 2270,909 2313,909 2228,944 2270,944 2313,944 2228,2034 2270,2034 2313,2034 2228,2069 2270,2069 2313,2069 2228,3159 2270,3159 2313,3159 2228,3194 2270,3194 2313,3194 2228,4284 2270,4284 2313,4284 2228,4319 2270,4319 2313,4319 659,4360 697,4360 735,4360 659,4402 697,4402 735,4402
VIN_PS: C34.1 C41.1 R15.2 R29.2 R33.2 U8.5 U9.2 | length 100.4
  Top Layer w20: v1(647,4235) 656.62,4235 664.62,4227 R15.2@686,4248.38 703.38,4231 v1(728,4231)
  other v1: 638,4197 672,4197 709,4197
  other v2: 248,3751 230,3784 270,3784 971,4276 1009,4276 1009,4313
